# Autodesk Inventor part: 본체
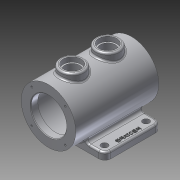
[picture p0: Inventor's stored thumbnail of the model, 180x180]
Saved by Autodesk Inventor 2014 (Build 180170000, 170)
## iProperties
Created: 2014-12
Part Number: 본체
Material: 알루미늄 6061
Document SubType Name: Modeling
Designer: Owner
Density: 2.71 g/cm^3
Appearance: 알루미늄 - 평지
Mass: 1293.91 g
Surface Area: 1040.15 cm^2
Volume: 477.456 cm^3
Author: Owner
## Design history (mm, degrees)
sketch "스케치4"
  geometry: L1 (65, -38)-(65, -50); L2 (65, -50)-(-65, -50); L3 (-65, -50)-(-65, -38); L4 (-65, -38)-(-38.884, -38); L5 (38.884, -38)-(65, -38); A1 r 46 centre (0, 0) between (35.072, -29.765) and (-35.072, -29.765); A2 r 5 centre (38.884, -33) between (35.072, -29.765) and (38.884, -38); A3 r 5 centre (-38.884, -33) between (-38.884, -38) and (-35.072, -29.765); 4 further points
  constraints: 10 end point, 8 point on circle, 4 tangent, 3 centre point, 3 parallel, 2 equal length, 2 horizontal, 2 perpendicular, 2 point on line, 1 coincident, 1 equal radius, 1 vertical alignment
  dimensions: "d8" = 92 diameter of A1; "d9" = 12 distance of L1.start L1.end; "d10" = 50 distance from line of L2 point (0, 0); "d11" = 130 distance of L1.end L2.end; "d12" = 5 radius of A2
extrude "돌출3" new body sketch "스케치4" stored distance "d13" = 95; taper "d14" = 0 deg
sketch "스케치5"
  geometry: C1 r 46 at (0, 0); A1 r 46 centre (0, 0) between (35.072, -29.765) and (-35.072, -29.765) reference
  constraints: 1 centre point, 1 coincident, 1 concentric
extrude "돌출4" join sketch "스케치5" distance "d15" = 30; taper "d16" = 0 deg
sketch "스케치6"
  geometry: C1 r 46 at (0, 0); A1 r 46 centre (0, 0) between (-35.072, 29.765) and (35.072, 29.765) reference
  constraints: 1 centre point, 1 coincident, 1 concentric
extrude "돌출5" join sketch "스케치6" distance "d17" = 15; taper "d18" = 0 deg
node "작업 평면2"
sketch "스케치7"
  geometry: L1 (-46, -77.5)-(46, -77.5) reference; C1 r 20 at (0, -37.5); C2 r 20 at (0, 22.5); 1 further point
  constraints: 2 centre point, 2 vertical alignment
  dimensions: "d20" = 40 diameter of C1; "d21" = 40 diameter of C2; "d22" = 40 distance from line of C1.centre L1; "d23" = 60 distance of C2.centre C1.centre
extrude "돌출6" join sketch "스케치7" stored distance "d24" = 15; taper "d25" = 0 deg
sketch "스케치8"
  geometry: C1 r 20 at (0, 0) reference; C2 r 15 at (0, 0); 1 further point
  constraints: 1 centre point, 1 coincident
  dimensions: "d26" = 30 diameter of C2
extrude "돌출7" cut sketch "스케치8" distance "d27" = 8; taper "d28" = 0 deg
sketch "스케치9"
  geometry: C1 r 20 at (0, 0) reference; C2 r 15 at (0, 0); 1 further point
  constraints: 1 centre point, 1 coincident
  dimensions: "d29" = 30 diameter of C2
extrude "돌출8" cut sketch "스케치9" distance "d30" = 8; taper "d31" = 0 deg
sketch "스케치11"
  geometry: C1 r 46 at (0, 0) reference; C2 r 30 at (0, 0)
  constraints: 1 centre point, 1 coincident
  dimensions: "d33" = 60 diameter of C2
extrude "돌출9" cut sketch "스케치11" distance "d34" = 12; taper "d35" = 0 deg
sketch "스케치12"
  geometry: C1 r 46 at (0, 0) reference; C2 r 30 at (0, 0)
  constraints: 1 centre point, 1 coincident
  dimensions: "d36" = 60 diameter of C2
extrude "돌출10" cut sketch "스케치12" distance "d37" = 12; taper "d38" = 0 deg
sketch "스케치13"
  geometry: C1 r 30 at (0, 0) reference; C2 r 37.5 at (0, 0)
  constraints: 1 centre point, 1 coincident
  dimensions: "d39" = 75 diameter of C2
extrude "돌출11" cut sketch "스케치13" distance "d40" = 116; taper "d41" = 0 deg
sketch "스케치14"
  geometry: C1 r 15 at (0, 0) reference; C2 r 12.5 at (0, 0); 1 further point
  constraints: 1 centre point, 1 coincident
  dimensions: "d42" = 25 diameter of C2
extrude "돌출12" cut sketch "스케치14" stored distance "d43" = 116; taper "d44" = 0 deg
sketch "스케치15"
  geometry: C1 r 15 at (0, 0) reference; C2 r 12.5 at (0, 0); 1 further point
  constraints: 1 centre point, 1 coincident
  dimensions: "d45" = 25 diameter of C2
extrude "돌출13" cut sketch "스케치15" stored distance "d46" = 116; taper "d47" = 0 deg
sketch "스케치16"
  geometry: L1 (26.116, 0)-(26.116, -95) reference; L2 (26.116, -95)-(0, -95) reference; C1 r 5.5 at (13.116, -82.5); 1 further point
  constraints: 1 centre point
  dimensions: "d48" = 11 diameter of C1; "d50" = 13 distance from line of C1.centre L1; "d51" = 12.5 distance from line of L2 C1.centre
extrude "돌출14" cut sketch "스케치16" stored distance "d52" = 116; taper "d53" = 0 deg
fillet "모깎기1" dims "d54" = 10
sketch "스케치17"
  geometry: L1 (26.116, 85)-(26.116, 10) reference; C1 r 5.5 at (13.116, 12.5) reference; 2 further points
  constraints: 1 other
  dimensions: "d55" = 35 vertical distance of point (18.116, 47.5) C1.centre; "d56" = 8 distance from line of point (18.116, 47.5) L1
feature "엠보싱1" sketch "스케치17" dims "d57" = 1, "d58" = 0
sketch "스케치18"
  geometry: L1 (0, 0)-(28.284, 28.284); L2 (0, 0)-(40, 0); C1 r 46 at (0, 0) reference; 1 further point
  constraints: 4 end point, 1 coincident, 1 equal length, 1 horizontal
  dimensions: "d59" = 40 distance of L1.start L1.end; "d60" = 45 deg angle of L2 L1
hole "구멍1" sketch "스케치18" at (28.284, 28.284) diameter "d61" = 3.242; stored, may be unused: countersink angle "d65" = 90 deg, drill point angle "d67" = 118 deg; dims "d62" = 8, "d63" = 4, "d64" = 2, "d66" = 10
sketch "스케치19"
  geometry: L1 (0, 0)-(28.284, 28.284); L2 (0, 0)-(40, 0); C1 r 46 at (0, 0) reference; 1 further point
  constraints: 4 end point, 1 coincident, 1 equal length, 1 horizontal
  dimensions: "d71" = 40 distance of L1.start L1.end; "d72" = 45 deg angle of L2 L1
hole "구멍2" sketch "스케치19" at (28.284, 28.284) diameter "d73" = 3.242; stored, may be unused: countersink angle "d77" = 90 deg, drill point angle "d79" = 118 deg; dims "d74" = 8, "d75" = 4, "d76" = 2, "d78" = 10
fillet "모깎기2" dims "d83" = 3
fillet "모깎기3" dims "d84" = 3
chamfer "모따기1" distance "d85" = 1; stored, may be unused: second distance "d86" = 2, angle "d87" = 45 deg
fillet "모깎기4" dims "d88" = 3
fillet "모깎기5" dims "d89" = 3
sketch "스케치21"
  geometry: 1 further point
node "솔리드2"
mirror "대칭1"
mirror "대칭2"
pattern_circular "원형 패턴1" dims angle "d69" = 360 deg
pattern_circular "원형 패턴2" dims angle "d81" = 360 deg
other parameters: "d19" = 56
